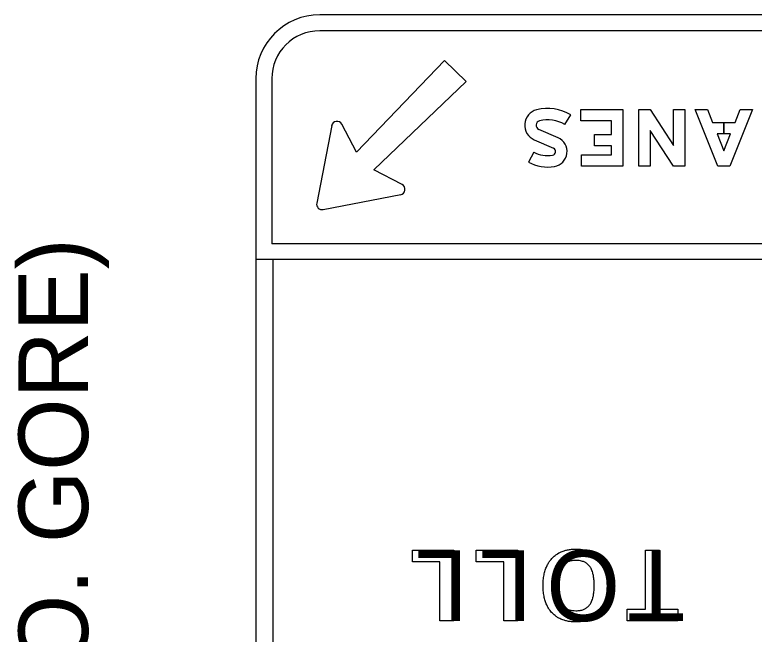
# Model space of a CAD drawing. Extents: x -102643 to -98250, y 54554 to 62384.
# Drawn here: x -102327.8 to -101962.7, y 58516.5 to 58822.4 of the extents above; entities that cross this region are included whole.
import ezdxf

# ---------------------------------------------------------------- set-up
doc = ezdxf.new("R2010")
doc.units = 0
doc.layers.add('SignPanel', color=7, linetype='Continuous')
doc.layers.add('TextLabel', color=7, linetype='Continuous')

msp = doc.modelspace()

# ---------------------------------------------------------------- linework, layer by layer
at = {"layer": 'SignPanel'}
for p, q in [((-101672.5, 58822.44), (-102177.25, 58822.44)), ((-101780.29, 58814.55), (-102177.25, 58814.55)), ((-102115.64, 58799.85), (-102159.05, 58754.57)), ((-102104.94, 58789.46), (-102115.64, 58799.85)), ((-102208.8, 58790.89), (-102208.8, 58333.46)), ((-102200.91, 58790.89), (-102200.91, 58709.4)), ((-102150.44, 58745.92), (-102104.94, 58789.46)), ((-102056.2, 58768.22), (-102053.29, 58773.02)), ((-102056.2, 58768.22), (-102053.29, 58773.02)), ((-102056.2, 58768.22), (-102053.29, 58773.02)), ((-102159.05, 58754.57), (-102166.39, 58768.5)), ((-102171.26, 58767.76), (-102178.7, 58729.46)), ((-102059.56, 58761.68), (-102069.06, 58765.84)), ((-102059.56, 58761.68), (-102069.06, 58765.84)), ((-102059.56, 58761.68), (-102069.06, 58765.84)), ((-102071.31, 58760.7), (-102061.81, 58756.54)), ((-102071.31, 58760.7), (-102061.81, 58756.54)), ((-102071.31, 58760.7), (-102061.81, 58756.54)), ((-102071.54, 58754.6), (-102074.19, 58749.66)), ((-102071.54, 58754.6), (-102074.19, 58749.66)), ((-102071.54, 58754.6), (-102074.19, 58749.66)), ((-102136.49, 58738.56), (-102150.44, 58745.92)), ((-102175.55, 58726.33), (-102137.23, 58733.72)), ((-101780.29, 58709.4), (-102200.91, 58709.4)), ((-101772.4, 58701.51), (-102208.8, 58701.51)), ((-102200.3, 58701.51), (-102200.3, 58333.46))]:
    msp.add_line(p, q, dxfattribs=at)
for points in [[(-102047.96, 58747.66), (-102047.96, 58753.27), (-102033.09, 58753.27), (-102033.09, 58757.75), (-102041.51, 58757.75), (-102041.51, 58763.36), (-102033.09, 58763.36), (-102033.09, 58770.1), (-102048.24, 58770.1), (-102048.24, 58775.71), (-102027.48, 58775.71), (-102027.48, 58747.66)], [(-102047.96, 58747.66), (-102047.96, 58753.27), (-102033.09, 58753.27), (-102033.09, 58757.75), (-102041.51, 58757.75), (-102041.51, 58763.36), (-102033.09, 58763.36), (-102033.09, 58770.1), (-102048.24, 58770.1), (-102048.24, 58775.71), (-102027.48, 58775.71), (-102027.48, 58747.66)], [(-102047.96, 58747.66), (-102047.96, 58753.27), (-102033.09, 58753.27), (-102033.09, 58757.75), (-102041.51, 58757.75), (-102041.51, 58763.36), (-102033.09, 58763.36), (-102033.09, 58770.1), (-102048.24, 58770.1), (-102048.24, 58775.71), (-102027.48, 58775.71), (-102027.48, 58747.66)], [(-101996.91, 58747.66), (-102002.52, 58747.66), (-102014.02, 58765.33), (-102014.02, 58747.66), (-102019.63, 58747.66), (-102019.63, 58775.71), (-102014.08, 58775.71), (-102002.52, 58757.94), (-102002.52, 58775.71), (-101996.91, 58775.71)], [(-101996.91, 58747.66), (-102002.52, 58747.66), (-102014.02, 58765.33), (-102014.02, 58747.66), (-102019.63, 58747.66), (-102019.63, 58775.71), (-102014.08, 58775.71), (-102002.52, 58757.94), (-102002.52, 58775.71), (-101996.91, 58775.71)], [(-101996.91, 58747.66), (-102002.52, 58747.66), (-102014.02, 58765.33), (-102014.02, 58747.66), (-102019.63, 58747.66), (-102019.63, 58775.71), (-102014.08, 58775.71), (-102002.52, 58757.94), (-102002.52, 58775.71), (-101996.91, 58775.71)], [(-101983.26, 58769.25), (-101972.13, 58769.25), (-101969.56, 58775.71), (-101963.53, 58775.71), (-101974.67, 58747.66), (-101980.71, 58747.66), (-101991.86, 58775.71), (-101985.82, 58775.71)], [(-101977.69, 58763.64), (-101977.69, 58769.25), (-101972.13, 58769.25), (-101969.56, 58775.71), (-101963.53, 58775.71), (-101974.67, 58747.66), (-101980.71, 58747.66), (-101991.86, 58775.71), (-101985.82, 58775.71), (-101983.26, 58769.25), (-101977.69, 58769.25), (-101977.69, 58763.64), (-101981.03, 58763.64), (-101977.69, 58755.25), (-101974.36, 58763.64)], [(-101977.69, 58763.64), (-101977.69, 58769.25), (-101972.13, 58769.25), (-101969.56, 58775.71), (-101963.53, 58775.71), (-101974.67, 58747.66), (-101980.71, 58747.66), (-101991.86, 58775.71), (-101985.82, 58775.71), (-101983.26, 58769.25), (-101977.69, 58769.25), (-101977.69, 58763.64), (-101981.03, 58763.64), (-101977.69, 58755.25), (-101974.36, 58763.64)], [(-101974.36, 58763.64), (-101981.03, 58763.64), (-101977.69, 58755.25)]]:
    msp.add_lwpolyline(points, close=True, dxfattribs=at)
for points in [[(-102111.06, 58557.97), (-102111.06, 58523.13), (-102117.84, 58523.13), (-102117.84, 58552.21), (-102131.48, 58552.21), (-102131.48, 58557.97), (-102111.06, 58557.97)], [(-102079.48, 58557.97), (-102079.48, 58523.13), (-102086.25, 58523.13), (-102086.25, 58552.21), (-102099.9, 58552.21), (-102099.9, 58557.97), (-102079.48, 58557.97)], [(-102016.29, 58528.93), (-102016.29, 58557.97), (-102009.47, 58557.97), (-102009.47, 58528.93), (-102000.32, 58528.93), (-102000.32, 58523.13), (-102025.48, 58523.13), (-102025.48, 58528.93), (-102016.29, 58528.93)]]:
    msp.add_lwpolyline(points, dxfattribs=at)
for centre, radius, start, end in [((-102177.25, 58790.89), 31.55, 90, 180), ((-102177.25, 58790.89), 23.66, 90, 180), ((-102068.16, 58767.9), 7.85, 104.4775, 246.3243), ((-102068.16, 58767.9), 7.85, 104.4775, 246.3243), ((-102068.16, 58767.9), 7.85, 104.4775, 246.3243), ((-102064.65, 58754.32), 21.88, 58.7193, 104.4775), ((-102064.65, 58754.32), 21.88, 58.7193, 104.4775), ((-102064.65, 58754.32), 21.88, 58.7193, 104.4775), ((-102168.69, 58767.13), 2.69, 27.9851, 169.0652), ((-102068.16, 58767.9), 2.24, 104.4775, 246.3243), ((-102068.16, 58767.9), 2.24, 104.4775, 246.3243), ((-102068.16, 58767.9), 2.24, 104.4775, 246.3243), ((-102064.65, 58754.32), 16.27, 58.7193, 104.4775), ((-102064.65, 58754.32), 16.27, 58.7193, 104.4775), ((-102064.65, 58754.32), 16.27, 58.7193, 104.4775), ((-102062.55, 58754.87), 7.43, 279.4877, 66.3243), ((-102062.55, 58754.87), 7.43, 279.4877, 66.3243), ((-102062.55, 58754.87), 7.43, 279.4877, 66.3243), ((-102064.65, 58767.46), 14.59, 241.8214, 279.4877), ((-102064.65, 58767.46), 14.59, 241.8214, 279.4877), ((-102064.65, 58767.46), 14.59, 241.8214, 279.4877), ((-102062.55, 58754.87), 1.82, 279.4877, 66.3243), ((-102062.55, 58754.87), 1.82, 279.4877, 66.3243), ((-102062.55, 58754.87), 1.82, 279.4877, 66.3243), ((-102064.65, 58767.46), 20.2, 241.8214, 279.4877), ((-102064.65, 58767.46), 20.2, 241.8214, 279.4877), ((-102064.65, 58767.46), 20.2, 241.8214, 279.4877), ((-102137.84, 58736.24), 2.69, 280.8535, 61.9362), ((-102176.08, 58728.9), 2.69, 169.0652, 280.8535)]:
    msp.add_arc(centre, radius, start, end, dxfattribs=at)
for points in [[(-102066.93, 58540.52), (-102066.92, 58541.22), (-102066.88, 58543.21), (-102066.52, 58545.8), (-102065.87, 58548.18), (-102065.16, 58550.05), (-102064.28, 58551.76), (-102063.35, 58553.07), (-102062.67, 58553.86), (-102061.96, 58554.61), (-102061, 58555.46), (-102059.72, 58556.34), (-102058.57, 58556.95), (-102057.6, 58557.37), (-102056.57, 58557.75), (-102054.93, 58558.2), (-102052.89, 58558.51), (-102051.4, 58558.55), (-102050.77, 58558.56)], [(-102050.77, 58558.56), (-102050.15, 58558.55), (-102048.65, 58558.51), (-102046.61, 58558.2), (-102044.96, 58557.75), (-102043.93, 58557.37), (-102042.95, 58556.95), (-102041.79, 58556.34), (-102040.51, 58555.46), (-102039.54, 58554.61), (-102038.82, 58553.86), (-102038.14, 58553.07), (-102037.37, 58551.99), (-102036.43, 58550.31), (-102035.68, 58548.45), (-102034.96, 58545.8), (-102034.6, 58543.21), (-102034.56, 58541.22), (-102034.55, 58540.52)], [(-102050.78, 58552.98), (-102051.2, 58552.97), (-102051.82, 58552.95), (-102052.81, 58552.83), (-102053.72, 58552.65), (-102054.56, 58552.36), (-102055.18, 58552.08), (-102055.74, 58551.76), (-102056.4, 58551.3), (-102057.1, 58550.66), (-102057.61, 58550.04), (-102057.96, 58549.51), (-102058.29, 58548.94), (-102058.74, 58548.01), (-102059.14, 58546.83), (-102059.5, 58545.15), (-102059.76, 58543.1), (-102059.8, 58541.41), (-102059.82, 58540.53)], [(-102041.7, 58540.53), (-102041.72, 58541.42), (-102041.76, 58543.12), (-102042.02, 58545.18), (-102042.38, 58546.86), (-102042.78, 58548.04), (-102043.22, 58548.96), (-102043.56, 58549.53), (-102043.91, 58550.06), (-102044.42, 58550.66), (-102045.12, 58551.31), (-102045.78, 58551.76), (-102046.34, 58552.08), (-102046.96, 58552.36), (-102047.81, 58552.65), (-102049.14, 58552.92), (-102050.15, 58552.95), (-102050.78, 58552.98)], [(-102050.77, 58522.58), (-102051.4, 58522.6), (-102052.91, 58522.63), (-102054.96, 58522.94), (-102056.62, 58523.4), (-102057.65, 58523.78), (-102058.63, 58524.2), (-102059.78, 58524.81), (-102061.06, 58525.69), (-102062.02, 58526.54), (-102062.72, 58527.28), (-102063.39, 58528.07), (-102064.31, 58529.38), (-102065.19, 58531.08), (-102065.88, 58532.94), (-102066.52, 58535.31), (-102066.88, 58537.86), (-102066.92, 58539.83), (-102066.93, 58540.52)], [(-102059.82, 58540.53), (-102059.8, 58539.65), (-102059.76, 58537.97), (-102059.5, 58535.92), (-102059.14, 58534.24), (-102058.74, 58533.07), (-102058.3, 58532.14), (-102057.96, 58531.58), (-102057.61, 58531.05), (-102057.1, 58530.44), (-102056.4, 58529.8), (-102055.74, 58529.34), (-102055.18, 58529.03), (-102054.56, 58528.74), (-102053.71, 58528.45), (-102052.38, 58528.18), (-102051.37, 58528.15), (-102050.74, 58528.13)], [(-102034.55, 58540.52), (-102034.56, 58539.83), (-102034.6, 58537.86), (-102034.95, 58535.31), (-102035.59, 58532.94), (-102036.1, 58531.59), (-102036.68, 58530.32), (-102037.34, 58529.15), (-102038.11, 58528.07), (-102038.79, 58527.28), (-102039.5, 58526.54), (-102040.48, 58525.69), (-102041.76, 58524.81), (-102042.92, 58524.2), (-102043.9, 58523.78), (-102044.93, 58523.4), (-102046.58, 58522.94), (-102048.64, 58522.63), (-102050.15, 58522.6), (-102050.77, 58522.58)], [(-102050.74, 58528.13), (-102050.32, 58528.14), (-102049.69, 58528.15), (-102048.69, 58528.27), (-102047.78, 58528.45), (-102046.94, 58528.74), (-102046.33, 58529.03), (-102045.76, 58529.34), (-102045.11, 58529.8), (-102044.41, 58530.44), (-102043.91, 58531.05), (-102043.56, 58531.58), (-102043.22, 58532.14), (-102042.78, 58533.07), (-102042.38, 58534.24), (-102042.02, 58535.92), (-102041.76, 58537.97), (-102041.72, 58539.65), (-102041.7, 58540.53)]]:
    msp.add_open_spline(points, degree=3, dxfattribs=at)

# ---------------------------------------------------------------- texts
for s, p in [('L', (-102104.08, 58557.97)), ('L', (-102104.08, 58557.97)), ('L', (-102072.49, 58557.97)), ('L', (-102072.49, 58557.97)), ('O', (-102028.96, 58557.97)), ('O', (-102028.96, 58557.97)), ('T', (-101996.82, 58557.97)), ('T', (-101996.82, 58557.97))]:
    msp.add_text(s, height=34.96, rotation=180, dxfattribs=at).set_placement(p)
at = {"layer": 'TextLabel'}
msp.add_text('(THEO. GORE)', height=34.335, rotation=90, dxfattribs=at).set_placement((-102291.63, 58393.19))

doc.saveas('drawing.dxf')
